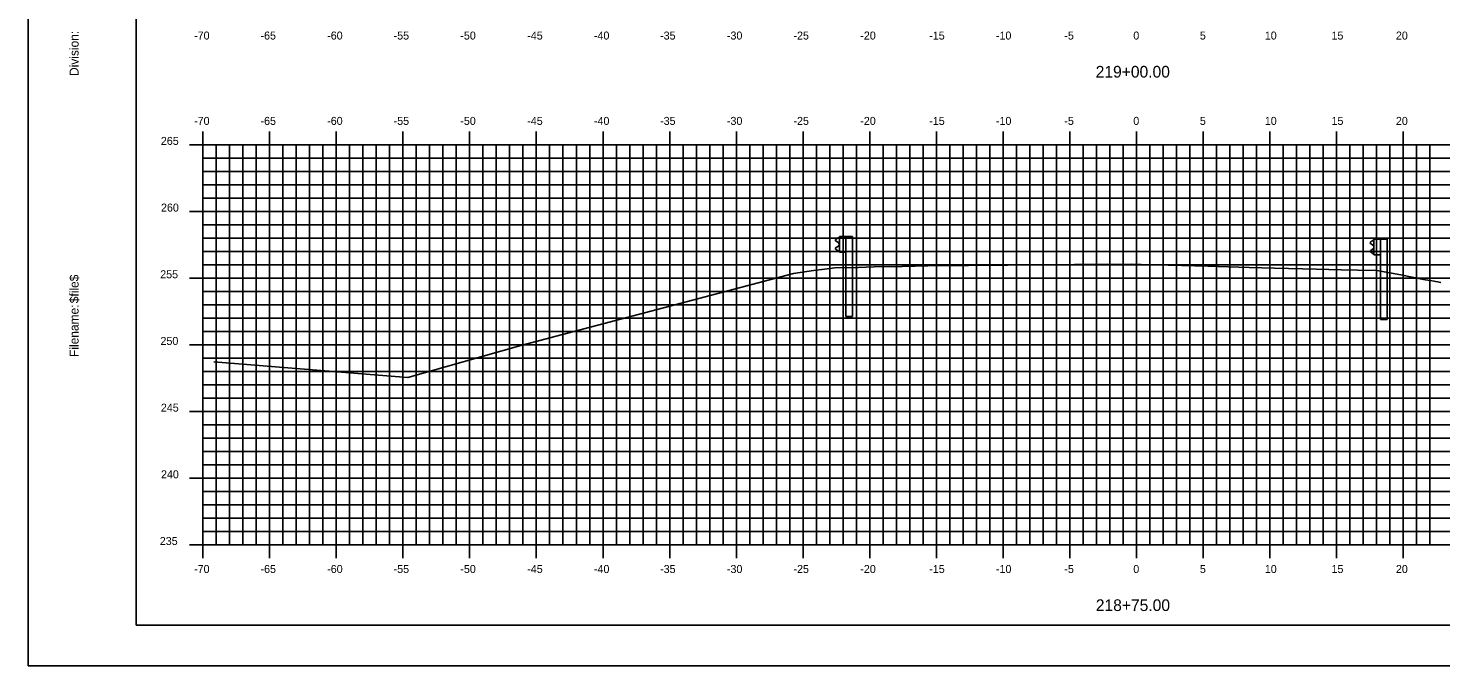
# Model space of a CAD drawing. Extents: x -22 to 1480, y -1511 to 8.
# Drawn here: x -22.2 to 83.8, y -184.5 to -136.7 of the extents above; entities that cross this region are included whole.
import ezdxf

# ---------------------------------------------------------------- set-up
doc = ezdxf.new("R2010")
doc.units = 0
for name, color, linetype in [('BORDER', 7, 'Continuous'), ('H_V ANNOTATION', 7, 'Continuous'), ('MAJOR', 7, 'Continuous'), ('MINOR', 7, 'Continuous'), ('PLOT BOUNDARY', 7, 'Continuous'), ('S_Guardrail_Beam', 7, 'Continuous'), ('S_Roadway_Centerline', 7, 'Continuous')]:
    doc.layers.add(name, color=color, linetype=linetype)

msp = doc.modelspace()

# ---------------------------------------------------------------- linework, layer by layer
at = {"layer": 'BORDER'}
for p, q in [((-14.06, -76.47), (-14.06, -181.47)), ((-14.06, -181.47), (145.94, -181.47))]:
    msp.add_line(p, q, dxfattribs=at)
at = {"layer": 'MAJOR'}
for p, q in [((-9.06, -144.46), (-9.06, -145.47)), ((-4.06, -144.46), (-4.06, -145.47)), ((0.94, -144.46), (0.94, -145.47)), ((5.94, -144.46), (5.94, -145.47)), ((10.94, -144.46), (10.94, -145.47)), ((15.94, -144.46), (15.94, -145.47)), ((20.94, -144.46), (20.94, -145.47)), ((25.94, -144.46), (25.94, -145.47)), ((30.94, -144.46), (30.94, -145.47)), ((35.94, -144.46), (35.94, -145.47)), ((40.94, -144.46), (40.94, -145.47)), ((45.94, -144.46), (45.94, -145.47)), ((50.94, -144.46), (50.94, -145.47)), ((55.94, -144.46), (55.94, -145.47)), ((60.94, -144.46), (60.94, -145.47)), ((65.94, -144.46), (65.94, -145.47)), ((70.94, -144.46), (70.94, -145.47)), ((75.94, -144.46), (75.94, -145.47)), ((80.94, -144.46), (80.94, -145.47)), ((-10.06, -145.47), (-9.06, -145.47)), ((-9.06, -145.47), (130.94, -145.47)), ((-9.06, -175.47), (-9.06, -145.47)), ((-9.06, -175.47), (-9.06, -145.47)), ((-9.06, -145.47), (130.94, -145.47)), ((-4.06, -175.47), (-4.06, -145.47)), ((0.94, -175.47), (0.94, -145.47)), ((5.94, -175.47), (5.94, -145.47)), ((10.94, -175.47), (10.94, -145.47)), ((15.94, -175.47), (15.94, -145.47)), ((20.94, -175.47), (20.94, -145.47)), ((25.94, -175.47), (25.94, -145.47)), ((30.94, -175.47), (30.94, -145.47)), ((35.94, -175.47), (35.94, -145.47)), ((40.94, -175.47), (40.94, -145.47)), ((45.94, -175.47), (45.94, -145.47)), ((50.94, -175.47), (50.94, -145.47)), ((55.94, -175.47), (55.94, -145.47)), ((60.94, -175.47), (60.94, -145.47)), ((65.94, -175.47), (65.94, -145.47)), ((70.94, -175.47), (70.94, -145.47)), ((75.94, -175.47), (75.94, -145.47)), ((80.94, -175.47), (80.94, -145.47)), ((-10.06, -150.47), (-9.06, -150.47)), ((-9.06, -150.47), (130.94, -150.47)), ((-10.06, -155.47), (-9.06, -155.47)), ((-9.06, -155.47), (130.94, -155.47)), ((-10.06, -160.47), (-9.06, -160.47)), ((-9.06, -160.47), (130.94, -160.47)), ((-10.06, -165.47), (-9.06, -165.47)), ((-9.06, -165.47), (130.94, -165.47)), ((-10.06, -170.47), (-9.06, -170.47)), ((-9.06, -170.47), (130.94, -170.47)), ((-10.06, -175.47), (-9.06, -175.47)), ((-9.06, -175.47), (130.94, -175.47)), ((-9.06, -175.47), (130.94, -175.47)), ((-9.06, -176.47), (-9.06, -175.47)), ((-4.06, -176.47), (-4.06, -175.47)), ((0.94, -176.47), (0.94, -175.47)), ((5.94, -176.47), (5.94, -175.47)), ((10.94, -176.47), (10.94, -175.47)), ((15.94, -176.47), (15.94, -175.47)), ((20.94, -176.47), (20.94, -175.47)), ((25.94, -176.47), (25.94, -175.47)), ((30.94, -176.47), (30.94, -175.47)), ((35.94, -176.47), (35.94, -175.47)), ((40.94, -176.47), (40.94, -175.47)), ((45.94, -176.47), (45.94, -175.47)), ((50.94, -176.47), (50.94, -175.47)), ((55.94, -176.47), (55.94, -175.47)), ((60.94, -176.47), (60.94, -175.47)), ((65.94, -176.47), (65.94, -175.47)), ((70.94, -176.47), (70.94, -175.47)), ((75.94, -176.47), (75.94, -175.47)), ((80.94, -176.47), (80.94, -175.47))]:
    msp.add_line(p, q, dxfattribs=at)
at = {"layer": 'MINOR'}
for p, q in [((-8.06, -175.47), (-8.06, -145.47)), ((-7.06, -175.47), (-7.06, -145.47)), ((-6.06, -175.47), (-6.06, -145.47)), ((-5.06, -175.47), (-5.06, -145.47)), ((-3.06, -175.47), (-3.06, -145.47)), ((-2.06, -175.47), (-2.06, -145.47)), ((-1.06, -175.47), (-1.06, -145.47)), ((-0.06, -175.47), (-0.06, -145.47)), ((1.94, -175.47), (1.94, -145.47)), ((2.94, -175.47), (2.94, -145.47)), ((3.94, -175.47), (3.94, -145.47)), ((4.94, -175.47), (4.94, -145.47)), ((6.94, -175.47), (6.94, -145.47)), ((7.94, -175.47), (7.94, -145.47)), ((8.94, -175.47), (8.94, -145.47)), ((9.94, -175.47), (9.94, -145.47)), ((11.94, -175.47), (11.94, -145.47)), ((12.94, -175.47), (12.94, -145.47)), ((13.94, -175.47), (13.94, -145.47)), ((14.94, -175.47), (14.94, -145.47)), ((16.94, -175.47), (16.94, -145.47)), ((17.94, -175.47), (17.94, -145.47)), ((18.94, -175.47), (18.94, -145.47)), ((19.94, -175.47), (19.94, -145.47)), ((21.94, -175.47), (21.94, -145.47)), ((22.94, -175.47), (22.94, -145.47)), ((23.94, -175.47), (23.94, -145.47)), ((24.94, -175.47), (24.94, -145.47)), ((26.94, -175.47), (26.94, -145.47)), ((27.94, -175.47), (27.94, -145.47)), ((28.94, -175.47), (28.94, -145.47)), ((29.94, -175.47), (29.94, -145.47)), ((31.94, -175.47), (31.94, -145.47)), ((32.94, -175.47), (32.94, -145.47)), ((33.94, -175.47), (33.94, -145.47)), ((34.94, -175.47), (34.94, -145.47)), ((36.94, -175.47), (36.94, -145.47)), ((37.94, -175.47), (37.94, -145.47)), ((38.94, -175.47), (38.94, -145.47)), ((39.94, -175.47), (39.94, -145.47)), ((41.94, -175.47), (41.94, -145.47)), ((42.94, -175.47), (42.94, -145.47)), ((43.94, -175.47), (43.94, -145.47)), ((44.94, -175.47), (44.94, -145.47)), ((46.94, -175.47), (46.94, -145.47)), ((47.94, -175.47), (47.94, -145.47)), ((48.94, -175.47), (48.94, -145.47)), ((49.94, -175.47), (49.94, -145.47)), ((51.94, -175.47), (51.94, -145.47)), ((52.94, -175.47), (52.94, -145.47)), ((53.94, -175.47), (53.94, -145.47)), ((54.94, -175.47), (54.94, -145.47)), ((56.94, -175.47), (56.94, -145.47)), ((57.94, -175.47), (57.94, -145.47)), ((58.94, -175.47), (58.94, -145.47)), ((59.94, -175.47), (59.94, -145.47)), ((61.94, -175.47), (61.94, -145.47)), ((62.94, -175.47), (62.94, -145.47)), ((63.94, -175.47), (63.94, -145.47)), ((64.94, -175.47), (64.94, -145.47)), ((66.94, -175.47), (66.94, -145.47)), ((67.94, -175.47), (67.94, -145.47)), ((68.94, -175.47), (68.94, -145.47)), ((69.94, -175.47), (69.94, -145.47)), ((71.94, -175.47), (71.94, -145.47)), ((72.94, -175.47), (72.94, -145.47)), ((73.94, -175.47), (73.94, -145.47)), ((74.94, -175.47), (74.94, -145.47)), ((76.94, -175.47), (76.94, -145.47)), ((77.94, -175.47), (77.94, -145.47)), ((78.94, -175.47), (78.94, -145.47)), ((79.94, -175.47), (79.94, -145.47)), ((81.94, -175.47), (81.94, -145.47)), ((82.94, -175.47), (82.94, -145.47)), ((-9.06, -146.47), (130.94, -146.47)), ((-9.06, -146.47), (-8.06, -146.47)), ((-9.06, -147.47), (130.94, -147.47)), ((-9.06, -147.47), (-8.06, -147.47)), ((-9.06, -148.47), (130.94, -148.47)), ((-9.06, -148.47), (-8.06, -148.47)), ((-9.06, -149.47), (130.94, -149.47)), ((-9.06, -149.47), (-8.06, -149.47)), ((-9.06, -151.47), (130.94, -151.47)), ((-9.06, -151.47), (-8.06, -151.47)), ((-9.06, -152.47), (130.94, -152.47)), ((-9.06, -152.47), (-8.06, -152.47)), ((-9.06, -153.47), (130.94, -153.47)), ((-9.06, -153.47), (-8.06, -153.47)), ((-9.06, -154.47), (130.94, -154.47)), ((-9.06, -154.47), (-8.06, -154.47)), ((-9.06, -156.47), (130.94, -156.47)), ((-9.06, -156.47), (-8.06, -156.47)), ((-9.06, -157.47), (130.94, -157.47)), ((-9.06, -157.47), (-8.06, -157.47)), ((-9.06, -158.47), (130.94, -158.47)), ((-9.06, -158.47), (-8.06, -158.47)), ((-9.06, -159.47), (130.94, -159.47)), ((-9.06, -159.47), (-8.06, -159.47)), ((-9.06, -161.47), (130.94, -161.47)), ((-9.06, -161.47), (-8.06, -161.47)), ((-9.06, -162.47), (130.94, -162.47)), ((-9.06, -162.47), (-8.06, -162.47)), ((-9.06, -163.47), (130.94, -163.47)), ((-9.06, -163.47), (-8.06, -163.47)), ((-9.06, -164.47), (130.94, -164.47)), ((-9.06, -164.47), (-8.06, -164.47)), ((-9.06, -166.47), (130.94, -166.47)), ((-9.06, -166.47), (-8.06, -166.47)), ((-9.06, -167.47), (130.94, -167.47)), ((-9.06, -167.47), (-8.06, -167.47)), ((-9.06, -168.47), (130.94, -168.47)), ((-9.06, -168.47), (-8.06, -168.47)), ((-9.06, -169.47), (130.94, -169.47)), ((-9.06, -169.47), (-8.06, -169.47)), ((-9.06, -171.47), (130.94, -171.47)), ((-9.06, -171.47), (-8.06, -171.47)), ((-9.06, -172.47), (130.94, -172.47)), ((-9.06, -172.47), (-8.06, -172.47)), ((-9.06, -173.47), (130.94, -173.47)), ((-9.06, -173.47), (-8.06, -173.47)), ((-9.06, -174.47), (130.94, -174.47)), ((-9.06, -174.47), (-8.06, -174.47))]:
    msp.add_line(p, q, dxfattribs=at)
at = {"layer": 'PLOT BOUNDARY'}
msp.add_lwpolyline([(-22.15, -184.53), (147.85, -184.53), (147.85, -74.53), (-22.15, -74.53)], close=True, dxfattribs=at)
at = {"layer": 'S_Guardrail_Beam'}
for p, q in [((38.56, -152.43), (38.41, -152.53)), ((38.66, -152.41), (38.57, -152.43)), ((38.66, -152.34), (39.14, -152.34)), ((38.66, -153.51), (38.66, -152.34)), ((39.14, -152.34), (39.64, -152.34)), ((39.14, -152.34), (39.14, -153.51)), ((39.64, -152.34), (39.64, -158.34)), ((38.41, -152.68), (38.61, -152.81)), ((38.61, -153.03), (38.41, -153.17)), ((38.41, -153.31), (38.56, -153.41)), ((38.57, -153.42), (38.66, -153.43)), ((38.64, -152.88), (38.64, -152.97)), ((39.14, -153.51), (38.66, -153.51)), ((39.14, -158.34), (39.14, -153.51)), ((78.65, -152.64), (78.5, -152.74)), ((78.5, -152.88), (78.7, -153.02)), ((78.7, -153.24), (78.5, -153.38)), ((78.5, -153.52), (78.65, -153.62)), ((78.74, -152.62), (78.66, -152.63)), ((78.73, -153.08), (78.73, -153.18)), ((78.74, -152.55), (79.23, -152.55)), ((78.74, -153.71), (78.74, -152.55)), ((79.23, -152.55), (79.73, -152.55)), ((79.23, -152.55), (79.23, -153.71)), ((79.73, -152.55), (79.73, -158.55)), ((78.66, -153.63), (78.74, -153.64)), ((79.23, -153.71), (78.74, -153.71)), ((79.23, -158.55), (79.23, -153.71)), ((39.14, -158.34), (39.64, -158.34)), ((79.23, -158.55), (79.73, -158.55))]:
    msp.add_line(p, q, dxfattribs=at)
for centre, major_axis, start_param, end_param in [((38.58, -152.47), (-0.0417, 0), 4.886922, 5.323254), ((38.46, -152.61), (-0.0877, 0), 5.323254, 7.243116), ((38.46, -153.24), (-0.0877, 0), 5.323254, 7.243116), ((38.58, -153.38), (-0.0417, 0), 0.959931, 1.396263), ((38.56, -152.88), (0.0789, 0), 0, 0.959931), ((38.56, -152.97), (0.0789, 0), 5.323254, 6.283185), ((78.55, -152.81), (-0.0877, 0), 5.323254, 7.243116), ((78.55, -153.45), (-0.0877, 0), 5.323254, 7.243116), ((78.67, -152.68), (-0.0417, 0), 4.886922, 5.323254), ((78.65, -153.08), (0.0789, 0), 0, 0.959931), ((78.65, -153.18), (0.0789, 0), 5.323254, 6.283185), ((78.67, -153.59), (-0.0417, 0), 0.959931, 1.396263)]:
    msp.add_ellipse(centre, major_axis=major_axis, ratio=0.995501, start_param=start_param, end_param=end_param, dxfattribs=at)
at = {"layer": 'S_Roadway_Centerline'}
msp.add_lwpolyline([(-8.23, -161.73), (3.47, -162.69), (6.3, -162.91), (14.78, -160.52), (35.22, -155.12), (36.71, -154.89), (37.54, -154.78), (38.32, -154.68), (40.06, -154.65), (41.28, -154.62), (43.38, -154.58), (46.28, -154.52), (48.34, -154.51), (51.28, -154.49), (53.3, -154.47), (56.28, -154.44), (58.76, -154.43), (60.6, -154.42), (61.15, -154.43), (61.28, -154.43), (64.35, -154.51), (66.28, -154.56), (69.39, -154.66), (71.28, -154.72), (74.43, -154.79), (76.28, -154.83), (77.53, -154.86), (78.95, -154.89), (80.75, -155.22), (82.47, -155.55), (82.93, -155.63), (83.25, -155.68), (83.36, -155.7), (83.53, -155.73), (83.73, -155.78), (83.75, -155.78)], dxfattribs=at)

# ---------------------------------------------------------------- texts
at = {"layer": 'BORDER'}
for s, p in [('Division:', (-18.38, -140.3)), ('$file$', (-18.38, -157.34)), ('Filename:', (-18.38, -161.37))]:
    msp.add_text(s, height=0.67, rotation=90, dxfattribs=at).set_placement(p)
at = {"layer": 'H_V ANNOTATION'}
for s, height, p in [('-70', 0.6, (-9.72, -137.57)), ('-65', 0.6, (-4.74, -137.57)), ('-60', 0.6, (0.26, -137.57)), ('-55', 0.6, (5.24, -137.57)), ('-50', 0.6, (10.24, -137.57)), ('-45', 0.6, (15.26, -137.57)), ('-40', 0.6, (20.26, -137.57)), ('-35', 0.6, (25.22, -137.57)), ('-30', 0.6, (30.23, -137.57)), ('-25', 0.6, (35.22, -137.57)), ('-20', 0.6, (40.23, -137.57)), ('-15', 0.6, (45.4, -137.57)), ('-10', 0.6, (50.4, -137.57)), ('-5', 0.6, (55.53, -137.57)), ('0', 0.6, (60.7, -137.57)), ('5', 0.6, (65.69, -137.57)), ('10', 0.6, (70.56, -137.57)), ('15', 0.6, (75.56, -137.57)), ('20', 0.6, (80.39, -137.57)), ('219+00.00', 0.875, (57.88, -140.42)), ('-70', 0.6, (-9.72, -143.97)), ('-65', 0.6, (-4.74, -143.97)), ('-60', 0.6, (0.26, -143.97)), ('-55', 0.6, (5.24, -143.97)), ('-50', 0.6, (10.24, -143.97)), ('-45', 0.6, (15.26, -143.97)), ('-40', 0.6, (20.26, -143.97)), ('-35', 0.6, (25.22, -143.97)), ('-30', 0.6, (30.23, -143.97)), ('-25', 0.6, (35.22, -143.97)), ('-20', 0.6, (40.23, -143.97)), ('-15', 0.6, (45.4, -143.97)), ('-10', 0.6, (50.4, -143.97)), ('-5', 0.6, (55.53, -143.97)), ('0', 0.6, (60.7, -143.97)), ('5', 0.6, (65.69, -143.97)), ('10', 0.6, (70.56, -143.97)), ('15', 0.6, (75.56, -143.97)), ('20', 0.6, (80.39, -143.97)), ('265', 0.6, (-12.21, -145.47)), ('260', 0.6, (-12.2, -150.47)), ('255', 0.6, (-12.26, -155.47)), ('250', 0.6, (-12.24, -160.47)), ('245', 0.6, (-12.21, -165.47)), ('240', 0.6, (-12.2, -170.47)), ('235', 0.6, (-12.29, -175.47)), ('-70', 0.6, (-9.72, -177.57)), ('-65', 0.6, (-4.74, -177.57)), ('-60', 0.6, (0.26, -177.57)), ('-55', 0.6, (5.24, -177.57)), ('-50', 0.6, (10.24, -177.57)), ('-45', 0.6, (15.26, -177.57)), ('-40', 0.6, (20.26, -177.57)), ('-35', 0.6, (25.22, -177.57)), ('-30', 0.6, (30.23, -177.57)), ('-25', 0.6, (35.22, -177.57)), ('-20', 0.6, (40.23, -177.57)), ('-15', 0.6, (45.4, -177.57)), ('-10', 0.6, (50.4, -177.57)), ('-5', 0.6, (55.53, -177.57)), ('0', 0.6, (60.7, -177.57)), ('5', 0.6, (65.69, -177.57)), ('10', 0.6, (70.56, -177.57)), ('15', 0.6, (75.56, -177.57)), ('20', 0.6, (80.39, -177.57)), ('218+75.00', 0.875, (57.89, -180.42))]:
    msp.add_text(s, height=height, dxfattribs=at).set_placement(p)

doc.saveas('drawing.dxf')
